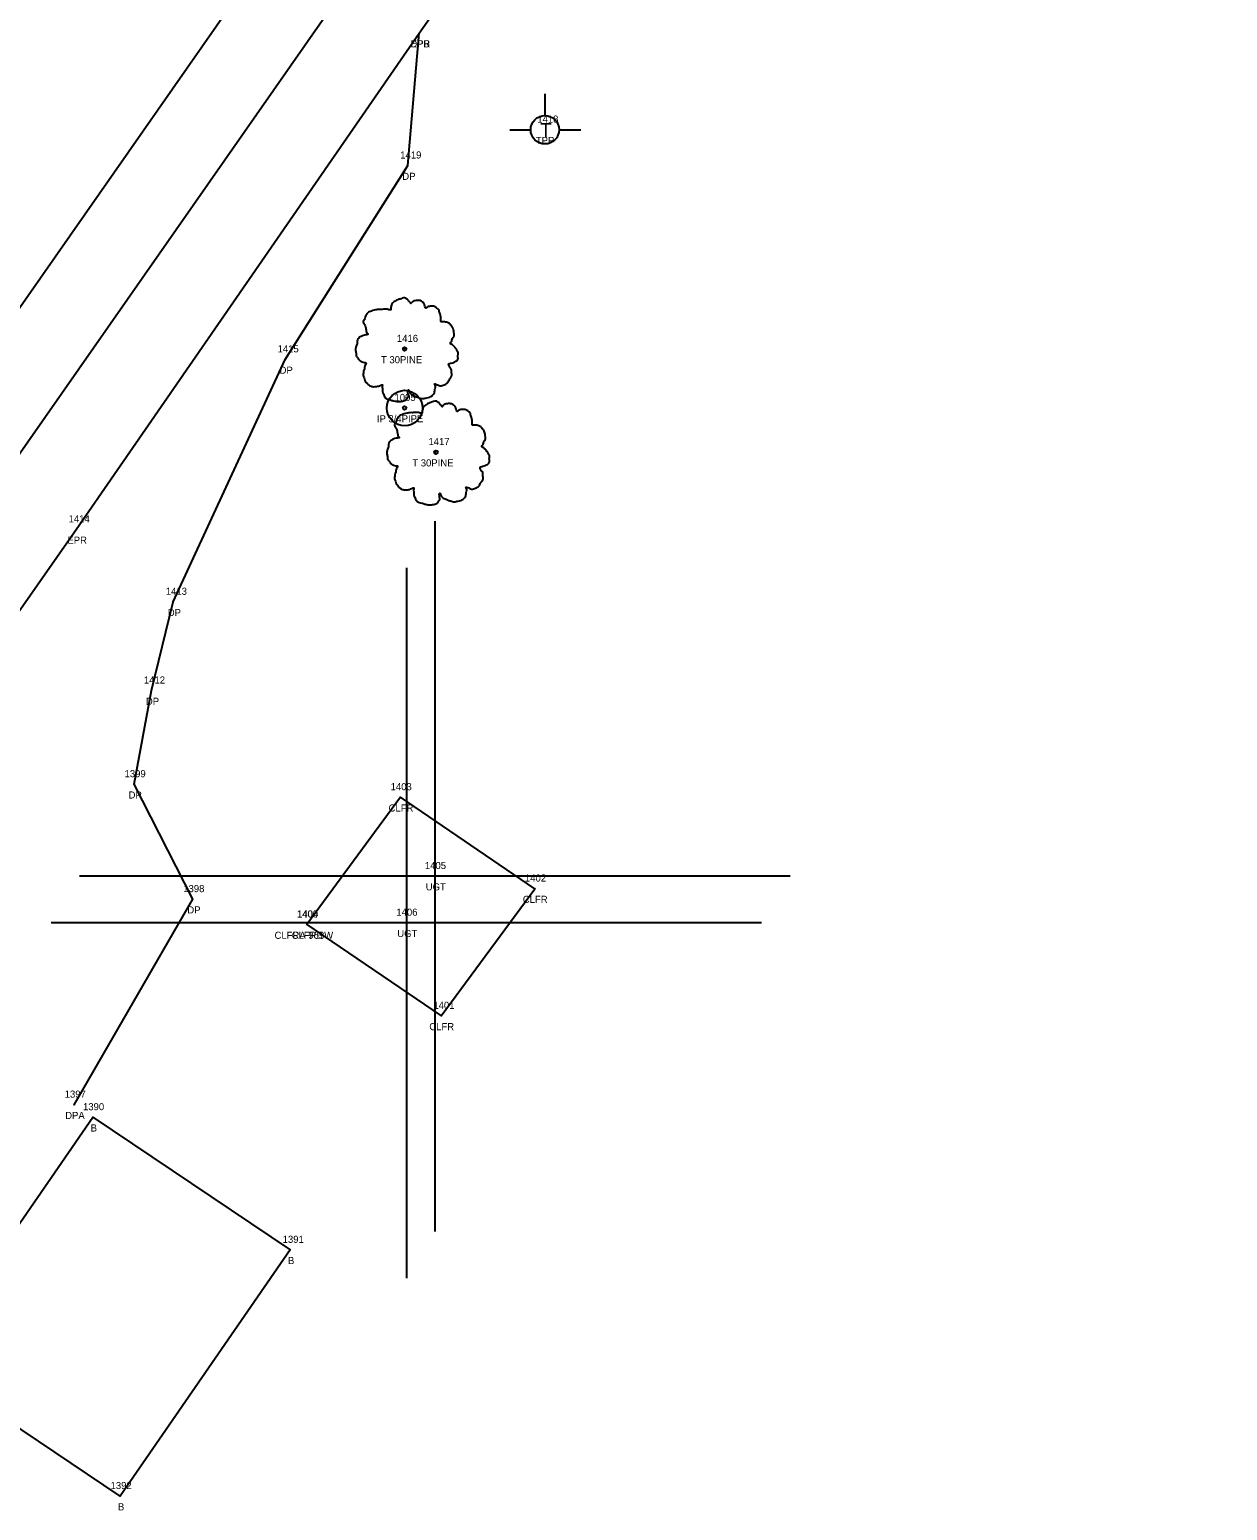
# Model space of a CAD drawing. Extents: x 2266664 to 2272542, y 716533 to 724777.
# Drawn here: x 2266797.4 to 2266966, y 716537.1 to 716745.6 of the extents above; entities that cross this region are included whole.
import ezdxf

# ---------------------------------------------------------------- set-up
doc = ezdxf.new("R2010")
doc.units = 0
for name, color, linetype in [('RD_EX_Bldg', 7, 'Continuous'), ('RD_EX_Bldg_txCode', 7, 'Continuous'), ('RD_EX_BldgApp_txCode', 7, 'Continuous'), ('RD_EX_Driveway', 7, 'Continuous'), ('RD_EX_Driveway_txCode', 7, 'Continuous'), ('RD_EX_DV_Prop_txCode', 7, 'Continuous'), ('RD_EX_DV_PropPin', 7, 'Continuous'), ('RD_EX_Fence_ChLk', 7, 'Continuous'), ('RD_EX_Fence_ChLk_txCode', 7, 'Continuous'), ('RD_EX_Road', 7, 'Continuous'), ('RD_EX_Road_txCode', 7, 'Continuous'), ('RD_EX_UT', 7, 'Continuous'), ('RD_EX_UT_txCode', 7, 'Continuous'), ('RD_EX_VEG', 7, 'Continuous'), ('RD_EX_VEG_txCode', 7, 'Continuous'), ('RD_HC_Cl', 7, 'Continuous'), ('RD_SMD_Locator', 7, 'Continuous')]:
    doc.layers.add(name, color=color, linetype=linetype)

msp = doc.modelspace()

# ---------------------------------------------------------------- linework, layer by layer
at = {"layer": 'RD_EX_Bldg'}
msp.add_lwpolyline([(2266782.39, 716557.79), (2266806.32, 716592.46), (2266834.09, 716573.79), (2266810.16, 716539.13), (2266782.39, 716557.79)], dxfattribs=at)
at = {"layer": 'RD_EX_Driveway'}
msp.add_lwpolyline([(2266803.69, 716594.23), (2266820.39, 716623.16), (2266812.12, 716639.34), (2266814.56, 716652.53), (2266817.64, 716665.02), (2266833.38, 716699.15), (2266850.64, 716726.44), (2266852.26, 716745.1)], dxfattribs=at)
at = {"layer": 'RD_EX_DV_PropPin'}
for radius in [2.5, 0.25]:
    msp.add_circle((2266850.2, 716692.31), radius, dxfattribs=at)
at = {"layer": 'RD_EX_Fence_ChLk'}
msp.add_lwpolyline([(2266836.45, 716619.59), (2266855.34, 716606.73), (2266868.51, 716624.65), (2266849.62, 716637.51), (2266836.45, 716619.59)], dxfattribs=at)
at = {"layer": 'RD_EX_Road'}
for points in [[(2266686.76, 716549.85), (2266747.4, 716636.84), (2266784.76, 716690.44), (2266841.99, 716772.31), (2266901.02, 716856.87), (2266959.75, 716940.59), (2267019.03, 717025.5), (2267078.68, 717111.16), (2267138.02, 717196.19), (2267176.19, 717250.98), (2267205.28, 717293.61), (2267251.45, 717360.21), (2267277.51, 717397.71), (2267309.59, 717444.12), (2267372.42, 717535.68), (2267423.33, 717609.72), (2267481.44, 717693.99), (2267537.28, 717775.3), (2267547.26, 717790.43), (2267554.32, 717803.83)], [(2266711.74, 716543.52), (2266760.73, 716613.35), (2266803.96, 716675.22), (2266852.26, 716745.1), (2266861.92, 716758.86), (2266897.35, 716809.34), (2266928.06, 716853.39), (2266979.23, 716926.79), (2267038.74, 717012.27), (2267098.79, 717098.14), (2267123.37, 717133.16), (2267147.47, 717167.75), (2267157.72, 717182.87), (2267214.02, 717263.41), (2267271.17, 717346.91), (2267311.09, 717404.37), (2267330.38, 717431.8), (2267384.12, 717510.57), (2267443.22, 717595.38), (2267501.41, 717680.42), (2267557.41, 717761.62), (2267564.52, 717772.38), (2267577.48, 717788.12)]]:
    msp.add_lwpolyline(points, dxfattribs=at)
at = {"layer": 'RD_EX_UT'}
for p, q in [((2266869.94, 716736.56), (2266869.94, 716733.49)), ((2266865.01, 716731.5), (2266867.94, 716731.5)), ((2266871.94, 716731.5), (2266875.01, 716731.5))]:
    msp.add_line(p, q, dxfattribs=at)
msp.add_circle((2266869.94, 716731.49), 2, dxfattribs=at)
at = {"layer": 'RD_EX_VEG'}
for centre, radius in [((2266850.2, 716700.62), 0.25), ((2266850.18, 716700.6), 0.0001), ((2266854.61, 716686.09), 0.25), ((2266854.6, 716686.07), 0.0001)]:
    msp.add_circle(centre, radius, dxfattribs=at)
for points in [[(2266850.33, 716707.79), (2266850.03, 716707.81), (2266849.7, 716707.71), (2266849.45, 716707.62), (2266849.23, 716707.54), (2266849, 716707.44), (2266848.7, 716707.27), (2266848.48, 716707.07), (2266848.35, 716706.82), (2266848.3, 716706.59), (2266848.25, 716706.32), (2266848.25, 716706.14), (2266848.13, 716706.12), (2266847.98, 716706.14), (2266847.73, 716706.22), (2266847.48, 716706.22), (2266847.23, 716706.22), (2266846.88, 716706.19), (2266846.53, 716706.19), (2266846.25, 716706.14), (2266845.93, 716706.09), (2266845.55, 716705.97), (2266845.2, 716705.84), (2266844.9, 716705.59), (2266844.65, 716705.12), (2266844.53, 716704.77), (2266844.38, 716704.52), (2266844.53, 716704.07), (2266844.7, 716703.72), (2266844.73, 716703.52), (2266844.8, 716703.09), (2266844.9, 716702.87), (2266845.03, 716702.67), (2266844.95, 716702.64), (2266844.58, 716702.59), (2266844.28, 716702.49), (2266843.86, 716702.27), (2266843.63, 716702.04), (2266843.53, 716701.72), (2266843.51, 716701.37), (2266843.41, 716701.17), (2266843.33, 716700.89), (2266843.31, 716700.82), (2266843.26, 716700.49), (2266843.36, 716700.04), (2266843.38, 716699.69), (2266843.51, 716699.47), (2266843.66, 716699.29), (2266843.83, 716699.04), (2266844.23, 716698.82), (2266844.55, 716698.72), (2266844.75, 716698.69), (2266844.58, 716698.19), (2266844.53, 716697.84), (2266844.4, 716697.44), (2266844.4, 716697.37), (2266844.35, 716696.89), (2266844.5, 716696.57), (2266844.58, 716696.2), (2266844.75, 716695.97), (2266845.03, 716695.67), (2266845.35, 716695.45), (2266845.85, 716695.32), (2266846.25, 716695.35), (2266846.83, 716695.52), (2266847.08, 716695.6), (2266847.05, 716695.42), (2266847.08, 716695.05), (2266847.08, 716694.62), (2266847.23, 716694.3), (2266847.33, 716694.02), (2266847.48, 716693.77), (2266847.8, 716693.55), (2266848.2, 716693.47), (2266848.63, 716693.32), (2266849.08, 716693.25), (2266849.58, 716693.22), (2266850.18, 716693.37), (2266850.45, 716693.5), (2266850.55, 716693.67), (2266850.75, 716694.05), (2266850.7, 716694.27), (2266850.73, 716694.87), (2266850.83, 716694.7), (2266851, 716694.35), (2266851.5, 716694.05), (2266851.9, 716693.87), (2266852.38, 716693.72), (2266852.68, 716693.65), (2266853.15, 716693.72), (2266853.53, 716693.8), (2266853.9, 716693.92), (2266854.2, 716694.2), (2266854.38, 716694.47), (2266854.43, 716694.75), (2266854.5, 716695.12), (2266854.55, 716695.3)], [(2266854.55, 716695.3), (2266854.48, 716695.47), (2266854.43, 716695.72), (2266854.5, 716695.7), (2266854.68, 716695.65), (2266854.95, 716695.52), (2266855.18, 716695.45), (2266855.5, 716695.47), (2266855.77, 716695.57), (2266856.22, 716695.85), (2266856.5, 716696.32), (2266856.77, 716696.72), (2266856.85, 716697.04), (2266856.8, 716697.27), (2266856.77, 716697.77), (2266856.57, 716698.02), (2266856.52, 716698.14), (2266856.42, 716698.54), (2266856.5, 716698.59), (2266856.77, 716698.64), (2266857.15, 716698.77), (2266857.42, 716698.89), (2266857.65, 716699.07), (2266857.72, 716699.29), (2266857.7, 716699.69), (2266857.75, 716700.09), (2266857.67, 716700.24), (2266857.57, 716700.39), (2266857.5, 716700.59), (2266857.35, 716700.74), (2266857.25, 716700.89), (2266857.15, 716700.99), (2266857.02, 716701.14), (2266856.85, 716701.27), (2266856.7, 716701.32), (2266856.65, 716701.47), (2266856.8, 716701.67), (2266856.85, 716701.77), (2266856.87, 716701.99), (2266857.1, 716702.34), (2266857.15, 716702.74), (2266857.1, 716703.17), (2266857.05, 716703.44), (2266856.9, 716703.72), (2266856.7, 716703.97), (2266856.57, 716704.14), (2266856.4, 716704.27), (2266856.07, 716704.39), (2266855.82, 716704.44), (2266855.47, 716704.44), (2266855.28, 716704.49), (2266855.3, 716704.54), (2266855.3, 716704.69), (2266855.3, 716704.97), (2266855.23, 716705.42), (2266855.08, 716705.92), (2266855.08, 716705.94), (2266854.98, 716706.19), (2266854.75, 716706.39), (2266854.58, 716706.49), (2266854.38, 716706.62), (2266854.13, 716706.64), (2266853.83, 716706.64), (2266853.55, 716706.59), (2266853.35, 716706.49), (2266853.18, 716706.37), (2266853.1, 716706.52), (2266853, 716706.82), (2266852.95, 716706.97), (2266852.8, 716707.14), (2266852.58, 716707.34), (2266852.13, 716707.47), (2266851.5, 716707.39), (2266851.2, 716707.19), (2266851.05, 716707.02), (2266851, 716707.14), (2266850.8, 716707.34), (2266850.7, 716707.52), (2266850.53, 716707.64), (2266850.38, 716707.74), (2266850.28, 716707.79)], [(2266854.74, 716693.26), (2266854.44, 716693.28), (2266854.12, 716693.18), (2266853.87, 716693.08), (2266853.64, 716693.01), (2266853.42, 716692.91), (2266853.12, 716692.73), (2266852.89, 716692.53), (2266852.77, 716692.28), (2266852.72, 716692.06), (2266852.67, 716691.78), (2266852.67, 716691.61), (2266852.54, 716691.58), (2266852.39, 716691.61), (2266852.14, 716691.68), (2266851.89, 716691.68), (2266851.64, 716691.68), (2266851.29, 716691.66), (2266850.94, 716691.66), (2266850.67, 716691.61), (2266850.34, 716691.56), (2266849.97, 716691.43), (2266849.62, 716691.31), (2266849.32, 716691.06), (2266849.07, 716690.58), (2266848.94, 716690.23), (2266848.79, 716689.98), (2266848.94, 716689.53), (2266849.12, 716689.18), (2266849.14, 716688.98), (2266849.22, 716688.56), (2266849.32, 716688.33), (2266849.44, 716688.13), (2266849.37, 716688.11), (2266848.99, 716688.06), (2266848.69, 716687.96), (2266848.27, 716687.74), (2266848.04, 716687.51), (2266847.94, 716687.19), (2266847.92, 716686.84), (2266847.82, 716686.64), (2266847.74, 716686.36), (2266847.72, 716686.29), (2266847.67, 716685.96), (2266847.77, 716685.51), (2266847.79, 716685.16), (2266847.92, 716684.94), (2266848.07, 716684.76), (2266848.24, 716684.51), (2266848.64, 716684.29), (2266848.97, 716684.19), (2266849.17, 716684.16), (2266848.99, 716683.66), (2266848.94, 716683.31), (2266848.82, 716682.91), (2266848.82, 716682.84), (2266848.77, 716682.36), (2266848.92, 716682.04), (2266848.99, 716681.66), (2266849.17, 716681.44), (2266849.44, 716681.14), (2266849.77, 716680.91), (2266850.27, 716680.79), (2266850.67, 716680.81), (2266851.24, 716680.99), (2266851.49, 716681.06), (2266851.47, 716680.89), (2266851.49, 716680.51), (2266851.49, 716680.09), (2266851.64, 716679.76), (2266851.74, 716679.49), (2266851.89, 716679.24), (2266852.22, 716679.01), (2266852.62, 716678.94), (2266853.04, 716678.79), (2266853.49, 716678.71), (2266853.99, 716678.69), (2266854.59, 716678.84), (2266854.87, 716678.96), (2266854.97, 716679.14), (2266855.17, 716679.51), (2266855.12, 716679.74), (2266855.14, 716680.34), (2266855.24, 716680.16), (2266855.42, 716679.81), (2266855.92, 716679.51), (2266856.32, 716679.34), (2266856.79, 716679.19), (2266857.09, 716679.11), (2266857.56, 716679.19), (2266857.94, 716679.26), (2266858.31, 716679.39), (2266858.61, 716679.66), (2266858.79, 716679.94), (2266858.84, 716680.21), (2266858.91, 716680.59), (2266858.96, 716680.76)], [(2266858.96, 716680.76), (2266858.89, 716680.94), (2266858.84, 716681.19), (2266858.91, 716681.16), (2266859.09, 716681.11), (2266859.36, 716680.99), (2266859.59, 716680.91), (2266859.91, 716680.94), (2266860.19, 716681.04), (2266860.64, 716681.31), (2266860.91, 716681.79), (2266861.19, 716682.19), (2266861.26, 716682.51), (2266861.21, 716682.74), (2266861.19, 716683.24), (2266860.99, 716683.49), (2266860.94, 716683.61), (2266860.84, 716684.01), (2266860.91, 716684.06), (2266861.19, 716684.11), (2266861.56, 716684.24), (2266861.84, 716684.36), (2266862.06, 716684.54), (2266862.14, 716684.76), (2266862.11, 716685.16), (2266862.16, 716685.56), (2266862.09, 716685.71), (2266861.99, 716685.86), (2266861.91, 716686.06), (2266861.76, 716686.21), (2266861.66, 716686.36), (2266861.56, 716686.46), (2266861.44, 716686.61), (2266861.26, 716686.74), (2266861.11, 716686.79), (2266861.06, 716686.94), (2266861.21, 716687.14), (2266861.26, 716687.24), (2266861.29, 716687.46), (2266861.51, 716687.81), (2266861.56, 716688.21), (2266861.51, 716688.63), (2266861.46, 716688.91), (2266861.31, 716689.18), (2266861.11, 716689.43), (2266860.99, 716689.61), (2266860.81, 716689.73), (2266860.49, 716689.86), (2266860.24, 716689.91), (2266859.89, 716689.91), (2266859.69, 716689.96), (2266859.71, 716690.01), (2266859.71, 716690.16), (2266859.71, 716690.43), (2266859.64, 716690.88), (2266859.49, 716691.38), (2266859.49, 716691.41), (2266859.39, 716691.66), (2266859.16, 716691.86), (2266858.99, 716691.96), (2266858.79, 716692.08), (2266858.54, 716692.11), (2266858.24, 716692.11), (2266857.96, 716692.06), (2266857.76, 716691.96), (2266857.59, 716691.83), (2266857.51, 716691.98), (2266857.41, 716692.28), (2266857.36, 716692.43), (2266857.21, 716692.61), (2266856.99, 716692.81), (2266856.54, 716692.93), (2266855.92, 716692.86), (2266855.62, 716692.66), (2266855.47, 716692.48), (2266855.42, 716692.61), (2266855.22, 716692.81), (2266855.12, 716692.98), (2266854.94, 716693.11), (2266854.79, 716693.21), (2266854.69, 716693.26)]]:
    msp.add_spline(points, degree=3, dxfattribs=at)
at = {"layer": 'RD_HC_Cl'}
msp.add_line((2266720.6, 716578.01), (2267109.6, 717134.74), dxfattribs=at)
at = {"layer": 'RD_SMD_Locator'}
for p, q in [((2266854.44, 716676.41), (2266854.44, 716576.41)), ((2266850.44, 716669.84), (2266850.44, 716569.84)), ((2266904.44, 716626.41), (2266804.44, 716626.41)), ((2266900.44, 716619.84), (2266800.44, 716619.84))]:
    msp.add_line(p, q, dxfattribs=at)
for centre in [(2266852.26, 716745.1), (2266852.26, 716745.1), (2266850.64, 716726.44), (2266833.38, 716699.15), (2266803.96, 716675.22), (2266817.64, 716665.02), (2266814.56, 716652.53), (2266812.12, 716639.34), (2266849.62, 716637.51), (2266820.39, 716623.16), (2266868.51, 716624.65), (2266836.45, 716619.59), (2266836.45, 716619.59), (2266855.34, 716606.73), (2266803.69, 716594.23), (2266806.32, 716592.46), (2266834.09, 716573.79), (2266810.16, 716539.13)]:
    msp.add_circle(centre, 0.001, dxfattribs=at)

# ---------------------------------------------------------------- texts
at = {"layer": 'RD_EX_Bldg_txCode'}
for s, p in [('1390', (2266804.93, 716593.46)), ('B', (2266806.01, 716590.46)), ('1391', (2266833.03, 716574.79)), ('B', (2266833.78, 716571.79)), ('1392', (2266808.81, 716540.13)), ('B', (2266809.85, 716537.13))]:
    msp.add_text(s, height=1, dxfattribs=at).set_placement(p)
at = {"layer": 'RD_EX_BldgApp_txCode'}
for s, p in [('1405', (2266853.05, 716627.41)), ('UGT', (2266853.17, 716624.41)), ('1406', (2266849.03, 716620.84)), ('UGT', (2266849.16, 716617.84))]:
    msp.add_text(s, height=1, dxfattribs=at).set_placement(p)
at = {"layer": 'RD_EX_Driveway_txCode'}
for s, p in [('DPB', (2266851.01, 716743.1)), ('1419', (2266849.58, 716727.44)), ('DP', (2266849.87, 716724.44)), ('1415', (2266832.32, 716700.15)), ('DP', (2266832.6, 716697.15)), ('1413', (2266816.58, 716666.02)), ('DP', (2266816.86, 716663.02)), ('1412', (2266813.5, 716653.53)), ('DP', (2266813.78, 716650.53)), ('1399', (2266810.78, 716640.34)), ('DP', (2266811.34, 716637.34)), ('1398', (2266819.04, 716624.16)), ('DP', (2266819.61, 716621.16)), ('1397', (2266802.35, 716595.23)), ('DPA', (2266802.42, 716592.23))]:
    msp.add_text(s, height=1, dxfattribs=at).set_placement(p)
at = {"layer": 'RD_EX_DV_Prop_txCode'}
for s, p in [('1005', (2266848.77, 716693.31)), ('IP 3/4PIPE', (2266846.29, 716690.31))]:
    msp.add_text(s, height=1, dxfattribs=at).set_placement(p)
at = {"layer": 'RD_EX_Fence_ChLk_txCode'}
for s, p in [('1403', (2266848.23, 716638.51)), ('CLFR', (2266847.94, 716635.51)), ('1402', (2266867.13, 716625.65)), ('CLFR', (2266866.83, 716622.65)), ('1400', (2266835.03, 716620.59)), ('1404', (2266835.07, 716620.59)), ('CLFRA 963W', (2266831.89, 716617.59)), ('CLFRB', (2266834.3, 716617.59)), ('1401', (2266854.24, 716607.73)), ('CLFR', (2266853.67, 716604.73))]:
    msp.add_text(s, height=1, dxfattribs=at).set_placement(p)
at = {"layer": 'RD_EX_Road_txCode'}
for s, p in [('EPR', (2266851.03, 716743.1)), ('1414', (2266802.9, 716676.22)), ('EPR', (2266802.73, 716673.22))]:
    msp.add_text(s, height=1, dxfattribs=at).set_placement(p)
at = {"layer": 'RD_EX_UT'}
msp.add_text('T', height=2, dxfattribs=at).set_placement((2266869.27, 716730.44))
at = {"layer": 'RD_EX_UT_txCode'}
for s, p in [('1418', (2266868.87, 716732.49)), ('TPP', (2266868.67, 716729.49))]:
    msp.add_text(s, height=1, dxfattribs=at).set_placement(p)
at = {"layer": 'RD_EX_VEG_txCode'}
for s, p in [('1416', (2266849.11, 716701.62)), ('T 30PINE', (2266846.87, 716698.62)), ('1417', (2266853.55, 716687.09)), ('T 30PINE', (2266851.28, 716684.09))]:
    msp.add_text(s, height=1, dxfattribs=at).set_placement(p)

doc.saveas('drawing.dxf')
